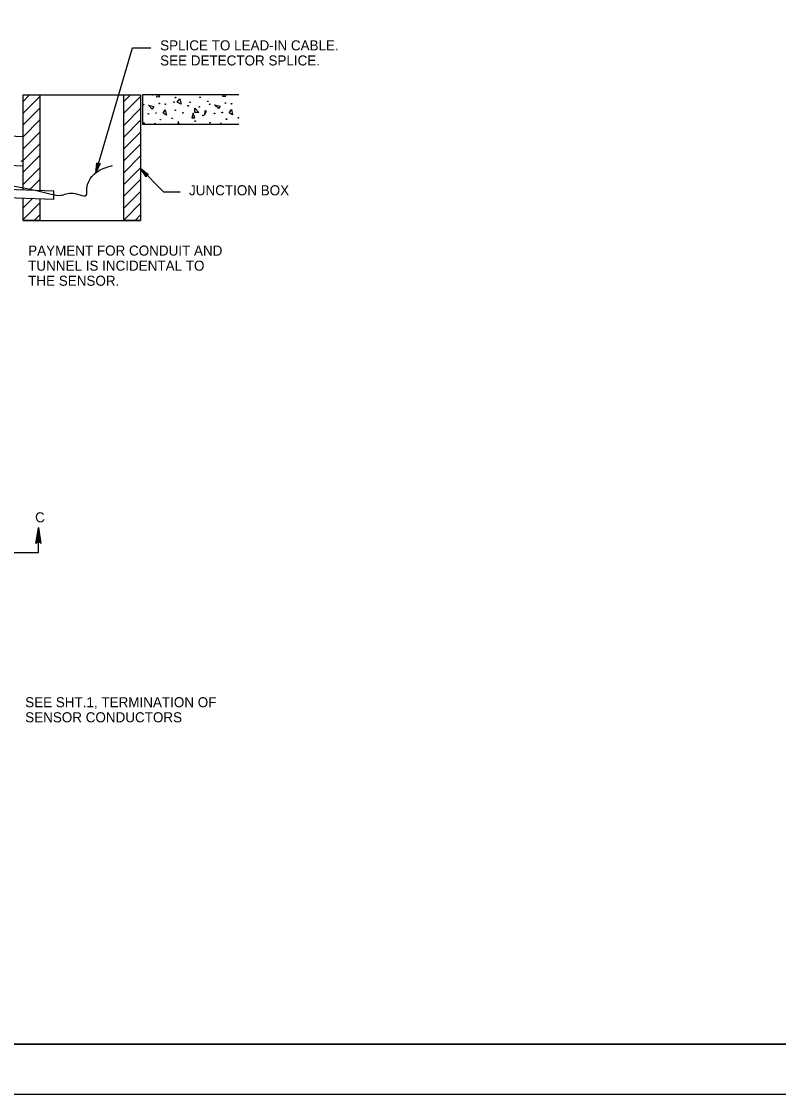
# Model space of a CAD drawing. Extents: x 2709 to 3899, y 22 to 1210.
# Drawn here: x 3030.6 to 3256.6, y 22.2 to 342.4 of the extents above; entities that cross this region are included whole.
import ezdxf

# ---------------------------------------------------------------- set-up
doc = ezdxf.new("R2010")
doc.units = 0
for name, color, linetype in [('1', 7, 'Continuous'), ('2', 7, 'Continuous'), ('3', 7, 'Continuous'), ('PLT-BNDY', 7, 'Continuous')]:
    doc.layers.add(name, color=color, linetype=linetype)

# ---------------------------------------------------------------- blocks, each defined once
blk = doc.blocks.new('RARROW')
at = {"layer": '3'}
blk.add_lwpolyline([(-2.2695, 0.285), (-2.184875, 0.12075), (0, 0), (-2.2695, 0.285), (-2.38575, 0.384625), (0, 0), (-2.183125, -0.108), (-2.262875, -0.2705), (0, 0), (-2.38575, -0.379125), (-2.262875, -0.2705)], dxfattribs=at)

msp = doc.modelspace()

# ---------------------------------------------------------------- linework, layer by layer
at = {"layer": '1'}
for p, q in [((3534.86, 37.17), (2748.86, 37.17)), ((2748.86, 37.17), (3334.86, 37.17))]:
    msp.add_line(p, q, dxfattribs=at)
at = {"layer": '2'}
for p, q in [((3052.8, 297.26), (3063.78, 334.54)), ((3063.78, 334.54), (3069.28, 334.54)), ((3031.15, 320.54), (3066.15, 320.54)), ((2816.4, 299.54), (3040.28, 291.92)), ((3066.15, 298.54), (3073.03, 291.54)), ((2816.4, 297.04), (3040.28, 289.42)), ((3040.28, 289.42), (3040.28, 291.92)), ((3073.03, 291.54), (3078.03, 291.54)), ((3031.15, 283.04), (3066.15, 283.04))]:
    msp.add_line(p, q, dxfattribs=at)
for points in [[(3031.15, 318.54), (3033.03, 320.54)], [(3031.15, 292.29), (3031.15, 320.54), (3036.15, 320.54), (3036.15, 292.04)], [(3061.15, 318.54), (3063.15, 320.54)], [(3095.53, 320.54), (3095.53, 320.54), (3066.78, 320.54), (3066.78, 311.79), (3095.53, 311.79), (3095.53, 311.79)], [(3071.03, 320.54), (3070.9, 319.92)], [(3071.9, 320.04), (3071.65, 320.54)], [(3090.78, 320.54), (3090.65, 320.17)], [(3091.65, 320.17), (3091.4, 320.54)], [(3031.15, 315.04), (3036.15, 320.04)], [(3061.15, 315.04), (3066.15, 320.04)], [(3070.9, 319.92), (3071.9, 320.04)], [(3090.65, 320.17), (3091.65, 320.17)], [(3031.15, 311.54), (3036.15, 316.54)], [(3061.15, 311.42), (3066.15, 316.42)], [(3031.15, 308.04), (3036.15, 313.04)], [(3061.15, 307.92), (3066.15, 312.92)], [(3070.4, 312.04), (3070.4, 311.79)], [(3070.53, 311.79), (3070.4, 312.04)], [(3077.4, 312.54), (3077.28, 311.79)], [(3077.78, 311.79), (3077.4, 312.54)], [(3090.15, 312.17), (3090.03, 311.79)], [(3090.28, 311.79), (3090.15, 312.17)], [(3031.15, 304.42), (3036.15, 309.42)], [(3061.15, 304.42), (3066.15, 309.42)], [(3031.15, 300.92), (3036.15, 305.92)], [(3061.15, 300.79), (3066.15, 305.79)], [(3031.15, 297.42), (3036.15, 302.42)], [(3061.15, 297.29), (3066.15, 302.29)], [(3031.15, 293.79), (3036.15, 298.79)], [(3061.15, 293.79), (3066.15, 298.79)], [(3033.03, 292.17), (3036.15, 295.29)], [(3061.15, 290.29), (3066.15, 295.29)], [(3061.15, 286.67), (3066.15, 291.67)], [(3036.15, 289.54), (3036.15, 283.04), (3031.15, 283.04), (3031.15, 289.79)], [(3031.15, 286.79), (3034.03, 289.67)], [(3031.15, 283.29), (3036.15, 288.29)], [(3061.15, 283.17), (3066.15, 288.17)], [(3034.4, 283.04), (3036.15, 284.67)], [(3064.53, 283.04), (3066.15, 284.67)], [(3028.22, 183.91), (3035.72, 183.91), (3035.72, 191.41)], [(3035.22, 186.79), (3035.47, 187.04), (3035.72, 191.41), (3035.22, 186.79), (3034.97, 186.66), (3035.72, 191.41), (3035.97, 187.04), (3036.35, 186.91), (3035.72, 191.41), (3036.47, 186.66), (3036.35, 186.91)]]:
    msp.add_lwpolyline(points, dxfattribs=at)
for points in [[(3066.15, 320.54), (3066.15, 283.04), (3061.15, 283.04), (3061.15, 320.54)], [(3070.15, 317.04), (3069.65, 316.29), (3068.53, 317.42)], [(3077.15, 318.29), (3077.9, 319.29), (3078.28, 317.79)], [(3089.9, 317.17), (3089.4, 316.42), (3088.28, 317.54)], [(3072.9, 315.04), (3073.53, 316.04), (3073.9, 314.42)], [(3081.9, 315.04), (3081.53, 313.67), (3082.4, 313.67)], [(3082.4, 315.29), (3082.4, 316.54), (3083.53, 315.29)], [(3085.9, 315.67), (3085.4, 315.79), (3085.28, 314.42)], [(3092.65, 315.17), (3093.28, 316.17), (3093.65, 314.54)], [(3031.15, 308.04), (2948.65, 311.79), (2948.65, 303.04), (3031.15, 299.29)]]:
    msp.add_lwpolyline(points, close=True, dxfattribs=at)
for centre in [(3069.84, 320.54), (3067.08, 317.57), (3071.76, 317.93), (3073.58, 317.73), (3076.14, 318.35), (3076.62, 319.7), (3080.4, 317.25), (3080.96, 318.31), (3083.71, 316.96), (3083.93, 319.8), (3086.27, 318.58), (3086.82, 317.71), (3091.5, 318.07), (3093.31, 317.87), (3068.5, 314.85), (3070.81, 315.11), (3076.57, 315.93), (3078.82, 315.16), (3084.84, 314.36), (3088.24, 314.99), (3090.54, 315.24), (3067.19, 312.06), (3072.09, 313.11), (3075.63, 313.52), (3082.48, 312.69), (3086.93, 312.2), (3091.82, 313.25), (3095.37, 313.66), (3030.76, 300.75)]:
    msp.add_circle(centre, 0.0919, dxfattribs=at)
msp.add_spline([(2860.78, 296.79), (2870.78, 296.42), (2877.4, 295.92), (2887.15, 295.29), (2901.78, 295.29), (3039.53, 290.92), (3042.28, 290.54), (3046.03, 291.17), (3050.15, 290.92), (3050.15, 291.42), (3050.4, 293.79), (3051.65, 296.17), (3053.4, 297.67), (3055.65, 298.79), (3057.78, 299.42)], degree=3, dxfattribs=at)
at = {"layer": 'PLT-BNDY'}
msp.add_lwpolyline([(2708.86, 616.17), (3549.86, 616.17), (3549.86, 22.17), (2708.86, 22.17)], close=True, dxfattribs=at)

# ---------------------------------------------------------------- block references
at = {"layer": '2', "xscale": 1.2574347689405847}
for p, yscale, rotation in [((3052.8, 297.26), 1.3092961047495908, -106.063702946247), ((3066.15, 298.54), 1.3092961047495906, 134.1588824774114)]:
    msp.add_blockref('RARROW', p, dxfattribs=dict(at, yscale=yscale, rotation=rotation))

# ---------------------------------------------------------------- texts
at = {"layer": '2'}
for s, p in [('SPLICE TO LEAD-IN CABLE.', (3072.03, 333.79)), ('SEE DETECTOR SPLICE.', (3072.03, 329.29)), ('JUNCTION BOX', (3080.65, 290.54)), ('PAYMENT FOR CONDUIT AND', (3032.65, 272.54)), ('TUNNEL IS INCIDENTAL TO', (3032.65, 268.04)), ('THE SENSOR.', (3032.65, 263.54)), ('SEE SHT.1, TERMINATION OF', (3031.76, 137.76)), ('SENSOR CONDUCTORS', (3031.76, 133.26))]:
    msp.add_text(s, height=3, dxfattribs=at).set_placement(p)
msp.add_text('C', height=3, rotation=5, dxfattribs=at).set_placement((3034.86, 192.81))

doc.saveas('drawing.dxf')
